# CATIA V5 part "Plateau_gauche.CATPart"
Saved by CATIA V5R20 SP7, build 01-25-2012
Part number: Plateau_gauche
Bounding box of the stored display mesh (mm): x -210 to -90, y -4.99 to 60, z -62.49 to 57.49
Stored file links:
  D:\IFMA\COURS\2A\projet balance IAO\catia\Plateau_gauche.CATPart
  D:\IFMA\COURS\2A\projet balance IAO\catia\Ass_projet_balance.CATProduct
  D:\IFMA\COURS\2A\projet balance IAO\catia\skl_barre_HEG.CATPart
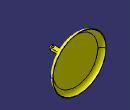
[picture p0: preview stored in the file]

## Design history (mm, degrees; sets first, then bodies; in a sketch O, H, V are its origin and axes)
Set1
  Plane1 "Plan_plateau_gauche": linked copy from another document
  Point1 "Point.K": linked copy from another document
  Point2 "Point.H": linked copy from another document
Body1 (main body)
  Sketch1 on Plane1, origin (0, 0, 0), H (1, 0, 0), V (0, 1, 0)
    arc A1 centre (-150, 0) radius 5 from (-155, 0) to (-145, 0) ccw
    point P1 (-150, 0)
    line L1 (-155, 0) -> (-155, 50)
    line L2 (-145, 0) -> (-145, 50)
    line L3 (-145, 50) -> (-155, 50)
    reference projected point E1 (-150, 30) from Point1
    reference projected point E2 (-150, 0) from Point2
    distance L2 L1 = 10
    distance L3 E1 = 20
    tangency: L1 A1, L2 A1
    vertical: L2 V
    horizontal: L3 H
    coincidence: P1 E2
  Pad1: profile Sketch1, direction (0, 0, -1), length 5
  Sketch2 on start face of Pad1, origin (0, 0, 0), H (1, 0, 0), V (0, 1, 0)
    circle A1 centre (-150, 0) radius 2.5
    point P1 (-150, 0)
    circle A2 centre (-150, 30) radius 2.5
    point P2 (-150, 30)
    reference projected point E1 (-150, 0) from Point2
    reference projected point E2 (-150, 30) from Point1
    radius A2 = 2.5
    radius A1 = 2.5
    coincidence: P1 E1, P2 E2
  Pocket1: profile Sketch2, direction (0, 0, -1), through (limit type 6)
  Sketch3 on face of Pad1 from Sketch1.L3, origin (0, 50, 0), H (-1, 0, 0), V (0, 0, 1)
    circle A1 centre (150, -2.5) radius 60
    point P1 (150, -2.5)
    reference projected point E1 (150, 0) from Point1
    reference projected point E2 (150, 0) from Point1
    radius A1 = 60
    distance P1 E1 H = 0
    distance P1 E2 V = 2.5
  Pad2: profile Sketch3, direction (0, 1, 0), length 10
  Sketch4 on end face of Pad2, origin (0, 60, 0), H (-1, 0, 0), V (0, 0, 1)
    circle A1 centre (150, -2.5) radius 59
    point P1 (150, -2.5)
    reference projected point E1 (150, 0) from Point1
    reference projected point E2 (150, 0) from Point1
    reference projected circle E3 centre (150, -2.5) radius 60 from edge [face of Pad2 from Sketch3.A1 | end face of Pad2]
    distance P1 E1 V = 2.5
    distance P1 E2 H = 0
    distance A1 E3 = 1
  Pocket2: profile Sketch4, direction (0, -1, 0), length 9
  Fillet1: radius 9, on end face of Pocket2
  Fillet2: radius 10, on edge [start face of Pad2 | face of Pad2 from Sketch3.A1]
